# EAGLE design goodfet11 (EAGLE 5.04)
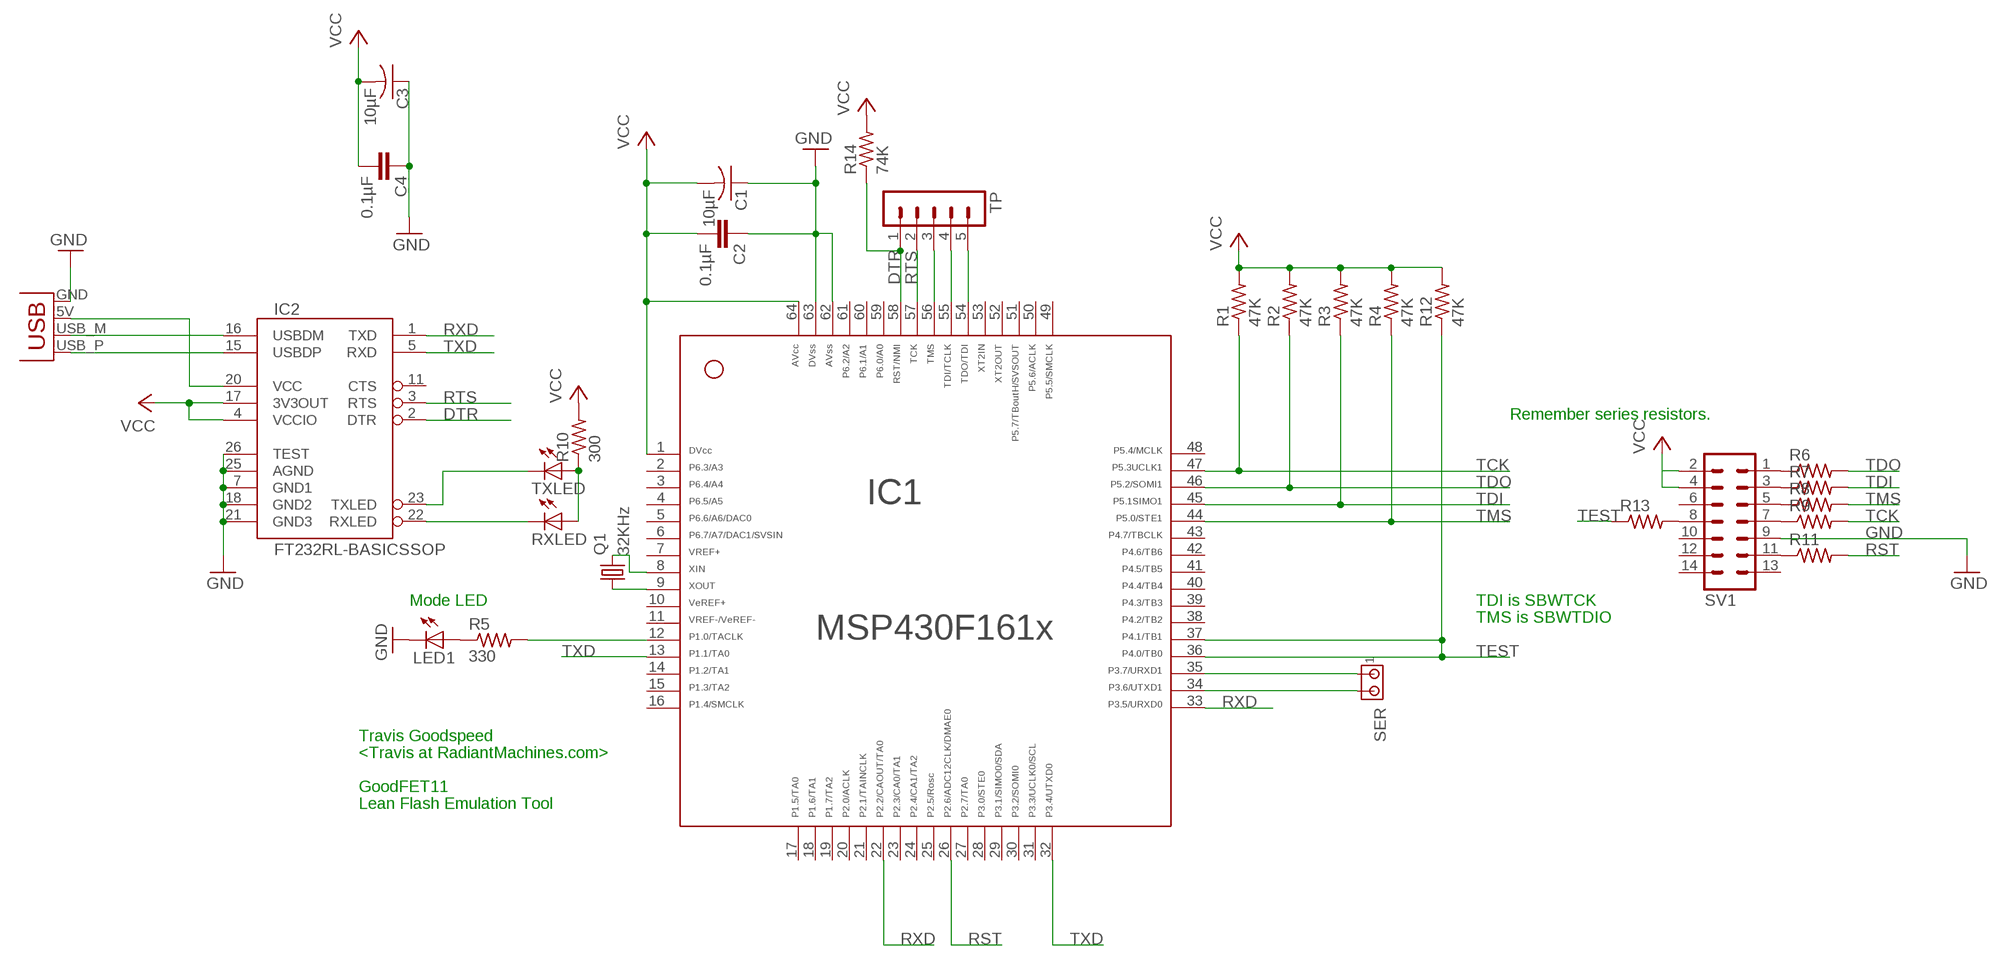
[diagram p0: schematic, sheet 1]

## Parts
C1  10µF  C-USC0603  [C0603]
C2  0.1µF  C-EUC0603  [C0603]
C3  10µF  C-USC0603  [C0603]
C4  0.1µF  C-EUC0603  [C0603]
IC1  F161X---PM64  [PM/PAG64]
IC2  FT232RL-BASICSSOP  [SSOP28DB]
LED1  LEDCHIP-LED0603  [CHIP-LED0603]
Q1  32KHz  CRYSTALTC26H  [TC26H]
R1  47K  R-US_R0603  [R0603]
R2  47K  R-US_R0603  [R0603]
R3  47K  R-US_R0603  [R0603]
R4  47K  R-US_R0603  [R0603]
R5  330  R-US_R0603  [R0603]
R6  R-US_R0603  [R0603]
R7  R-US_R0603  [R0603]
R8  R-US_R0603  [R0603]
R9  R-US_R0603  [R0603]
R10  300  R-US_R0603  [R0603]
R11  R-US_R0603  [R0603]
R12  47K  R-US_R0603  [R0603]
R13  R-US_R0603  [R0603]
R14  74K  R-US_R0603  [R0603]
RXLED  LEDCHIP-LED0603  [CHIP-LED0603]
SER  MTA02-100  [10X02MTA]
SV1  MA07-2  [MA07-2]
TP  MA05-1  [MA05-1]
TXLED  LEDCHIP-LED0603  [CHIP-LED0603]
X1  USBPCB  [USB-A-PCB]

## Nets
DTR: IC1.58 IC2.2(DTR) R14.1 TP.1
GND: C1.1 C2.1 C3.1 C4.1 IC1.62 IC1.63 IC2.7(GND1) IC2.18(GND2) IC2.21(GND3) IC2.25(AGND) IC2.26(TEST) LED1.C SV1.9 X1.GND
N$1: IC1.12 R5.2
N$2: LED1.A R5.1
N$3: IC2.15(USBDP) X1.USB_P(D+)
N$4: IC2.16(USBDM) X1.USB_M(D-)
N$5: IC2.20(VCC) X1.5V(VBUS)
N$6: IC2.22(RXLED) RXLED.C
N$7: IC2.23(TXLED) TXLED.C
N$8: R10.1 RXLED.A TXLED.A
N$9: IC1.35 SER.1
N$10: IC1.34 SER.2
N$11: IC1.56 TP.3
N$12: IC1.55 TP.4
N$13: IC1.54 TP.5
N$14: R6.1 SV1.1
N$15: R7.1 SV1.3
N$16: R8.1 SV1.5
N$17: R9.1 SV1.7
N$18: R11.1 SV1.11
N$19: R13.2 SV1.8
N$20: IC1.9 Q1.1
N$21: IC1.8 Q1.2
RST: IC1.26 R11.2
RTS: IC1.57 IC2.3(RTS) TP.2
RXD: IC1.22 IC1.33 IC2.1(TXD)
TCK: IC1.47 R1.1 R9.2
TDI: IC1.45 R3.1 R7.2
TDO: IC1.46 R2.1 R6.2
TEST: IC1.36 IC1.37 R12.1 R13.1
TMS: IC1.44 R4.1 R8.2
TXD: IC1.13 IC1.32 IC2.5(RXD)
VCC: C1.2 C2.2 C3.2 C4.2 IC1.1 IC1.64 IC2.4(VCCIO) IC2.17(3V3OUT) R1.2 R2.2 R3.2 R4.2 R10.2 R12.2 R14.2 SV1.2 SV1.4
Unconnected: IC1.2 IC1.3 IC1.4 IC1.5 IC1.6 IC1.7 IC1.10 IC1.11 IC1.14 IC1.15 IC1.16 IC1.17 IC1.18 IC1.19 IC1.20 IC1.21 IC1.23 IC1.24 IC1.25 IC1.27 IC1.28 IC1.29 IC1.30 IC1.31 IC1.38 IC1.39 IC1.40 IC1.41 IC1.42 IC1.43 IC1.48 IC1.49 IC1.50 IC1.51 IC1.52 IC1.53 IC1.59 IC1.60 IC1.61 IC2.11(CTS) SV1.6 SV1.10 SV1.12 SV1.13 SV1.14

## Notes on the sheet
- Remember series resistors.
- Mode LED | TDI is SBWTCK
- TMS is SBWTDIO
- Travis Goodspeed
- <Travis at RadiantMachines.com>
- GoodFET11
- Lean Flash Emulation Tool

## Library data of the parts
C1 C3 = rcl:C-US: CAPACITOR, American symbol
C2 C4 = rcl:C-EU: CAPACITOR, European symbol
IC1 = TI_MSP430_v122:F161X---PM64: *** MSP430F161x *** PM64
IC2 = SparkFun:FT232RL-BASIC: USB UART This is the simplified version of the FT232RL unit. Only what you need, nothing you don't. Spark Fun Electronics SKU : COM-00650
LED1 RXLED TXLED = led:LED: LED
Q1 = SparkFun:CRYSTAL: Crystals
R1-R5 R10 R12 R14 = rcl:R-US_: RESISTOR, American symbol
R6-R9 R11 R13 = resistor:R-US_: RESISTOR, American symbol
SER = con-amp:MTA02-100: AMP connector
SV1 = con-lstb:MA07-2: PIN HEADER
TP = con-lstb:MA05-1: PIN HEADER
X1 = SparkFun:USB: USB Connectors USB-B-PTH is fully proven SKU : PRT-00139 USB-miniB is fully proven SKU : PRT-00587 USB-A-PCB is untested. USB-A-H is throughly reviewed, but untested. Spark Fun Electronics SKU : PRT-00437 USB-B-SMT is throughly reviewed, but untested. Needs silkscreen touching up. USB-A-S has not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

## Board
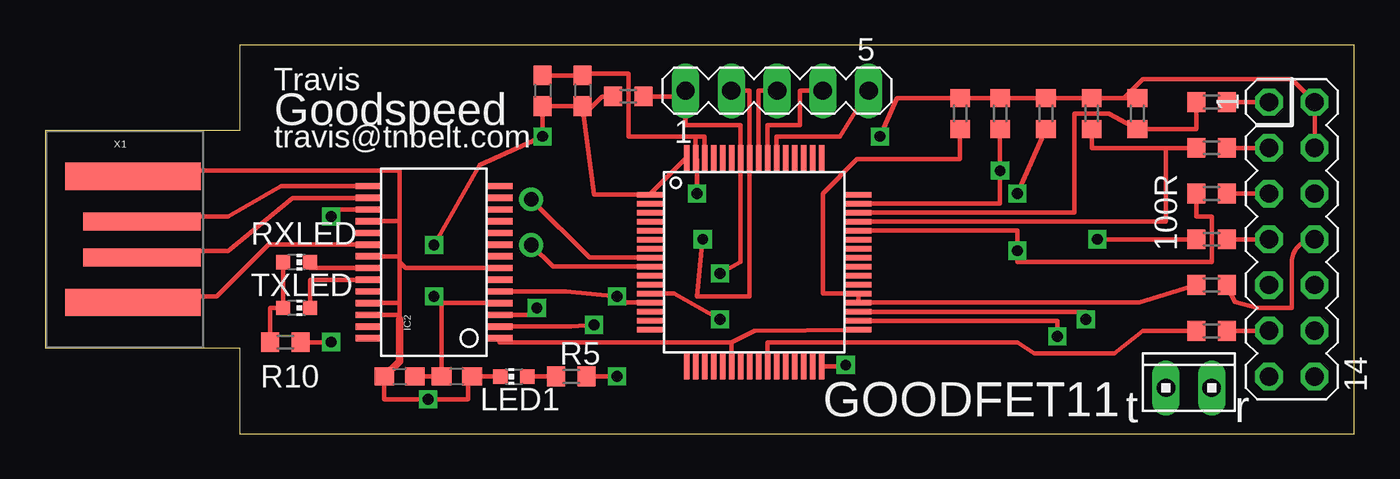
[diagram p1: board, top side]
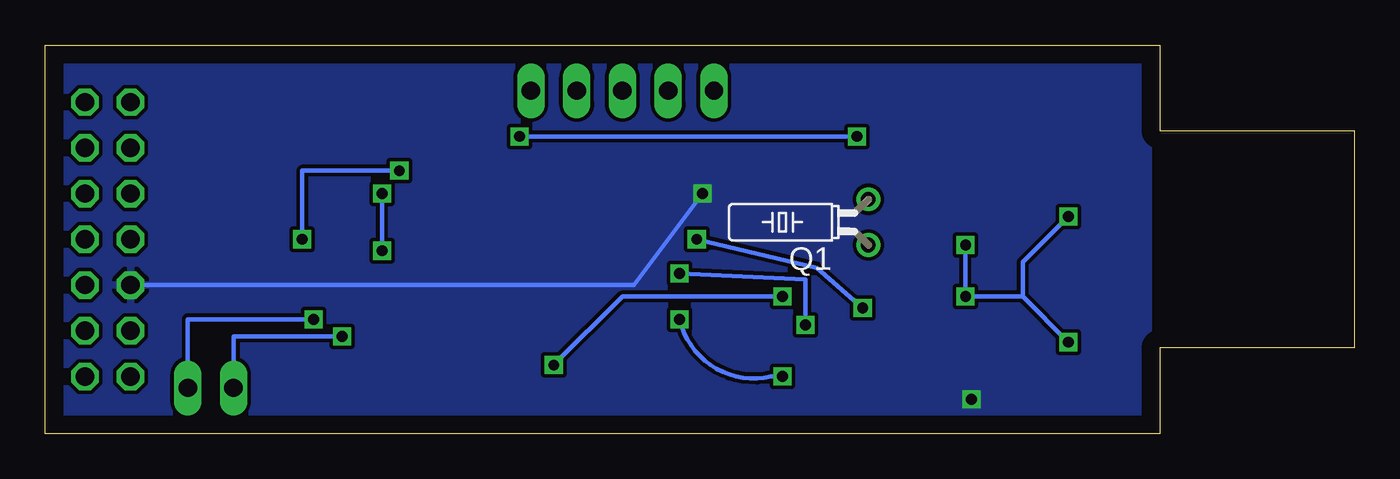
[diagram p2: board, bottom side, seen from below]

Size 72.69 x 21.59 mm. Coordinates in mm from the lower left corner, seen from the top.
Outline: 10.79,0 72.69,0 72.69,21.59 10.79,21.59 10.79,16.83 0,16.83 0,4.76 10.79,4.76 10.79,0
Copper layers (1*16): Top 0.035mm / dielectric 1.5mm / Bottom 0.035mm
Design rules "default": minimum track width 10mil, minimum drill 24mil, track to track 8mil, track to pad 8mil, pad to pad 8mil, via to via 8mil, smd to smd 8mil, copper to edge 40mil, drill to drill 8mil, minimum pad ring 10mil, minimum via ring 8mil, stop-mask expansion 4mil, vias tented up to drill 0mil, thermal gap 10mil

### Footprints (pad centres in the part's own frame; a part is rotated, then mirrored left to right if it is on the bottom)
C0603 = smd 1.1 x 1: 1 -0.85,0; 2 0.85,0
PM/PAG64 = smd 1.4 x 0.3: 1 -5.8,3.75; 2 -5.8,3.25; 3 -5.8,2.75; 4 -5.8,2.25; 5 -5.8,1.75; 6 -5.8,1.25; 7 -5.8,0.75; 8 -5.8,0.25; 9 -5.8,-0.25; 10 -5.8,-0.75; 11 -5.8,-1.25; 12 -5.8,-1.75; 13 -5.8,-2.25; 14 -5.8,-2.75; 15 -5.8,-3.25; 16 -5.8,-3.75; 33 5.8,-3.75; 34 5.8,-3.25; 35 5.8,-2.75; 36 5.8,-2.25; 37 5.8,-1.75; 38 5.8,-1.25; 39 5.8,-0.75; 40 5.8,-0.25; 41 5.8,0.25; 42 5.8,0.75; 43 5.8,1.25; 44 5.8,1.75; 45 5.8,2.25; 46 5.8,2.75; 47 5.8,3.25; 48 5.8,3.75 | smd 0.3 x 1.4: 17 -3.75,-5.8; 18 -3.25,-5.8; 19 -2.75,-5.8; 20 -2.25,-5.8; 21 -1.75,-5.8; 22 -1.25,-5.8; 23 -0.75,-5.8; 24 -0.25,-5.8; 25 0.25,-5.8; 26 0.75,-5.8; 27 1.25,-5.8; 28 1.75,-5.8; 29 2.25,-5.8; 30 2.75,-5.8; 31 3.25,-5.8; 32 3.75,-5.8; 49 3.75,5.8; 50 3.25,5.8; 51 2.75,5.8; 52 2.25,5.8; 53 1.75,5.8; 54 1.25,5.8; 55 0.75,5.8; 56 0.25,5.8; 57 -0.25,5.8; 58 -0.75,5.8; 59 -1.25,5.8; 60 -1.75,5.8; 61 -2.25,5.8; 62 -2.75,5.8; 63 -3.25,5.8; 64 -3.75,5.8
SSOP28DB = smd 0.348 x 1.397: 1 -4.225,-3.656; 2 -3.575,-3.656; 3 -2.925,-3.656; 4 -2.275,-3.656; 5 -1.625,-3.656; 6 -0.975,-3.656; 7 -0.325,-3.656; 8 0.325,-3.656; 9 0.975,-3.656; 10 1.625,-3.656; 11 2.275,-3.656; 12 2.925,-3.656; 13 3.575,-3.656; 14 4.225,-3.656; 15 4.225,3.656; 16 3.575,3.656; 17 2.925,3.656; 18 2.275,3.656; 19 1.625,3.656; 20 0.975,3.656; 21 0.325,3.656; 22 -0.325,3.656; 23 -0.975,3.656; 24 -1.625,3.656; 25 -2.275,3.656; 26 -2.925,3.656; 27 -3.575,3.656; 28 -4.225,3.656
CHIP-LED0603 = smd 0.8 x 0.8: A 0,-0.75; C 0,0.75
TC26H = drill 0.813 round: 1 -1.27,0; 2 1.27,0
R0603 = smd 1 x 1.1: 1 -0.85,0; 2 0.85,0
10X02MTA = drill 1.016 long: 1 1.27,0; 2 -1.27,0
MA07-2 = drill 1.016 octagon: 1 -7.62,-1.27; 2 -7.62,1.27; 3 -5.08,-1.27; 4 -5.08,1.27; 5 -2.54,-1.27; 6 -2.54,1.27; 7 0,-1.27; 8 0,1.27; 9 2.54,-1.27; 10 2.54,1.27; 11 5.08,-1.27; 12 5.08,1.27; 13 7.62,-1.27; 14 7.62,1.27
MA05-1 = drill 1.016 long: 1 -5.08,0; 2 -2.54,0; 3 0,0; 4 2.54,0; 5 5.08,0
USB-A-PCB = smd 7.5 x 1.5: 5V -0.2,-3.5; GND -0.2,3.5 | smd 6.5 x 1: USB_M 0.3,-1; USB_P 0.3,1

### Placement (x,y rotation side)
C1  27.62,19.05 270 top
C2  29.85,19.05 270 top
C3  19.68,3.18 0 top
C4  22.86,3.18 180 top
IC1  39.37,9.53 0 top
IC2  21.59,9.53 90 top
LED1  26.04,3.18 90 top
Q1  26.99,11.75 90 bottom
R1  53.02,17.78 90 top
R2  60.64,17.78 90 top
R3  58.1,17.78 90 top
R4  55.56,17.78 90 top
R5  29.21,3.18 0 top
R6  64.77,18.42 180 top
R7  64.77,15.88 180 top
R8  64.77,13.33 180 top
R9  64.77,10.79 180 top
R10  13.33,5.08 0 top
R11  64.77,5.71 180 top
R12  50.8,17.78 90 top
R13  64.77,8.25 0 top
R14  32.39,18.73 180 top
RXLED  13.97,9.53 270 top
SER  63.5,2.54 0 top
SV1  69.21,10.79 270 top
TP  40.64,19.05 0 top
TXLED  13.97,6.99 270 top
X1  5.08,10.79 0 top

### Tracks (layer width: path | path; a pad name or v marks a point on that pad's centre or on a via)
DTR  (via drill 0.6)
  Top 0.254: IC2.2 29.21,5.95 v30.48,6.03 | v37.47,8.89 38.62,9.53 IC1.58 38.62,17.14 35.56,17.14 TP.1 35.56,18.73 R14.1
  Bottom 0.254: v30.48,6.03 30.48,8.57 v37.47,8.89
GND  (via drill 0.6)
  Top 0.254: 19.68,11.8 19.68,14.61 5.2,14.61 X1.GND | 19.68,11.8 IC2.18 | 19.68,11.8 19.68,10.16 | 19.68,10.16 19.68,9.53 | 19.68,9.53 19.68,7.62 | 19.68,7.62 19.68,6.6 | 19.68,6.6 IC2.26 | 19.68,6.6 19.68,6.35 | IC2.25 19.68,7.25 19.68,7.62 | IC2.21 19.68,9.85 19.68,10.16 | C3.1 18.83,1.91 v21.27,1.91 23.49,1.91 23.49,3.18 C4.1 LED1.C | IC2.7 20.01,9.2 19.68,9.53 | C1.1 C2.1 29.85,20 32.39,20 32.39,16.51 36.12,16.51 | 36.12,16.51 IC1.63 36.2,15.25 v36.2,13.33 | IC1.62 36.62,16.51 36.12,16.51
  Top 0.406: 19.68,6.35 19.68,4.03 C3.1
  Bottom 0.254: SV1.9 40.01,8.25 v36.2,13.33
  pour Bottom: 12.06,21.27 72.07,21.27 72.07,0.95 11.43,0.95 11.43,20.64
N$1  (via drill 0.6)
  Top 0.254: R5.2 v31.75,3.18 | v37.47,6.35 34.93,7.78 IC1.12
  Bottom 0.254: v31.75,3.18 32.39,3.18 arc90 v37.47,6.35
N$2
  Top 0.254: LED1.A R5.1
N$3
  Top 0.254: IC2.15 13.11,13.75 10.16,12.07 5.65,12.07 X1.USB_P
N$4
  Top 0.254: IC2.16 13.73,13.1 10.16,10.16 5.75,10.16 X1.USB_M
N$5
  Top 0.254: IC2.20 12.4,10.5 9.52,7.62 5.2,7.62 X1.5V
N$6
  Top 0.254: IC2.22 14.72,9.2 RXLED.C
N$7
  Top 0.254: IC2.23 14.72,8.55 TXLED.C
N$8
  Top 0.254: RXLED.A TXLED.A 12.48,6.99 R10.1
N$9  (via drill 0.6)
  Top 0.254: IC1.35 57.79,6.78 v57.79,6.35
  Bottom 0.254: v57.79,6.35 64.77,6.35 SER.1
N$10  (via drill 0.6)
  Top 0.254: IC1.34 56.2,6.28 v56.2,5.4
  Bottom 0.254: v56.2,5.4 62.23,5.4 SER.2
N$11
  Top 0.254: IC1.56 39.62,19.05 TP.3
N$12
  Top 0.254: IC1.55 40.12,17.14 41.91,17.14 41.91,19.05 TP.4
N$13
  Top 0.254: IC1.54 40.62,16.51 44.13,16.51 TP.5
N$14
  Top 0.254: R6.1 SV1.1
N$15
  Top 0.254: R7.1 SV1.3
N$16
  Top 0.254: R8.1 SV1.5
N$17
  Top 0.254: R9.1 SV1.7
N$18
  Top 0.254: R11.1 SV1.11
N$19
  Top 0.254: R13.2 66.04,7.3 67.31,6.99 69.21,6.99 69.21,9.53 arc-90 SV1.8
N$20
  Top 0.254: IC1.9 28.19,9.28 Q1.1
N$21
  Top 0.254: IC1.8 30.23,9.78 Q1.2
RST
  Top 0.254: IC1.26 40.12,5.08 53.98,5.08 54.93,4.45 59.37,4.45 60.96,5.71 R11.2
RTS  (via drill 0.6)
  Top 0.254: TP.2 39.12,19.05 IC1.57 39.12,7.62 36.2,7.62 v36.51,10.79 | IC2.3 27.3,6.6 v27.3,6.99
  Bottom 0.254: v27.3,6.99 29.85,9.21 v36.51,10.79
RXD
  Top 0.254: IC2.1 25.25,5.08 38.1,5.08 | 38.1,5.08 39.4,5.71 IC1.33 | IC1.22 38.12,5.08 38.1,5.08
TCK  (via drill 0.6)
  Top 0.254: IC1.47 53.02,12.78 v53.02,14.61 R1.1 | 64.13,10.79 R9.2 v58.42,10.79
  Bottom 0.254: v58.42,10.79 58.42,14.61 v53.02,14.61
TDI
  Top 0.254: 62.23,15.88 58.1,15.88 R3.1 | 62.23,15.88 R7.2 | IC1.45 62.23,11.78 62.23,15.88
TDO
  Top 0.254: R6.2 63.92,16.93 R2.1 59.05,17.78 57.15,17.78 57.15,12.28 IC1.46
TEST
  Top 0.254: R13.1 60.74,7.28 IC1.36 IC1.37 43.18,7.78 43.18,13.33 45.09,15.24 50.8,15.24 R12.1
TMS  (via drill 0.6)
  Top 0.254: IC1.44 53.98,11.28 v53.98,10.16 53.98,9.53 64.77,9.53 64.77,12.07 63.92,12.07 R8.2 | v53.98,13.33 R4.1
  Bottom 0.254: v53.98,10.16 v53.98,13.33
TXD  (via drill 0.6)
  Top 0.254: IC1.32 44.37,3.72 v44.45,3.81 | IC2.5 28.93,7.9 v31.75,7.62 31.75,7.28 IC1.13
  Bottom 0.254: v44.45,3.81 40.64,7.62 v31.75,7.62
VCC  (via drill 0.6)
  Top 0.254: C3.2 C4.2 22.01,7.25 | 22.01,7.25 IC2.4 | R10.2 v15.88,5.08 | 22.01,7.25 21.96,7.25 v21.59,7.62 | v15.88,12.07 16.26,12.45 IC2.17 | 29.91,17.71 C2.2 C1.2 v27.62,16.51 24.13,14.92 v21.59,10.48 | 29.91,17.71 30.48,13.28 IC1.1 IC1.64 | SV1.4 SV1.2 69.21,19.68 60.96,19.68 59.91,18.63 R2.2 R3.2 R4.2 R1.2 R12.2 47.31,18.63 v46.36,16.51 | R14.2 30.93,18.73 29.91,17.71
  Bottom 0.254: 18.41,7.62 v21.59,7.62 v21.59,10.48 | v15.88,5.08 18.41,7.62 | 18.41,7.62 18.41,9.53 v15.88,12.07 | v27.62,16.51 v46.36,16.51

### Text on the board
tPlace: Travis | Goodspeed | travis@tnbelt.com | 100R | GOODFET11
tNames: t | r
